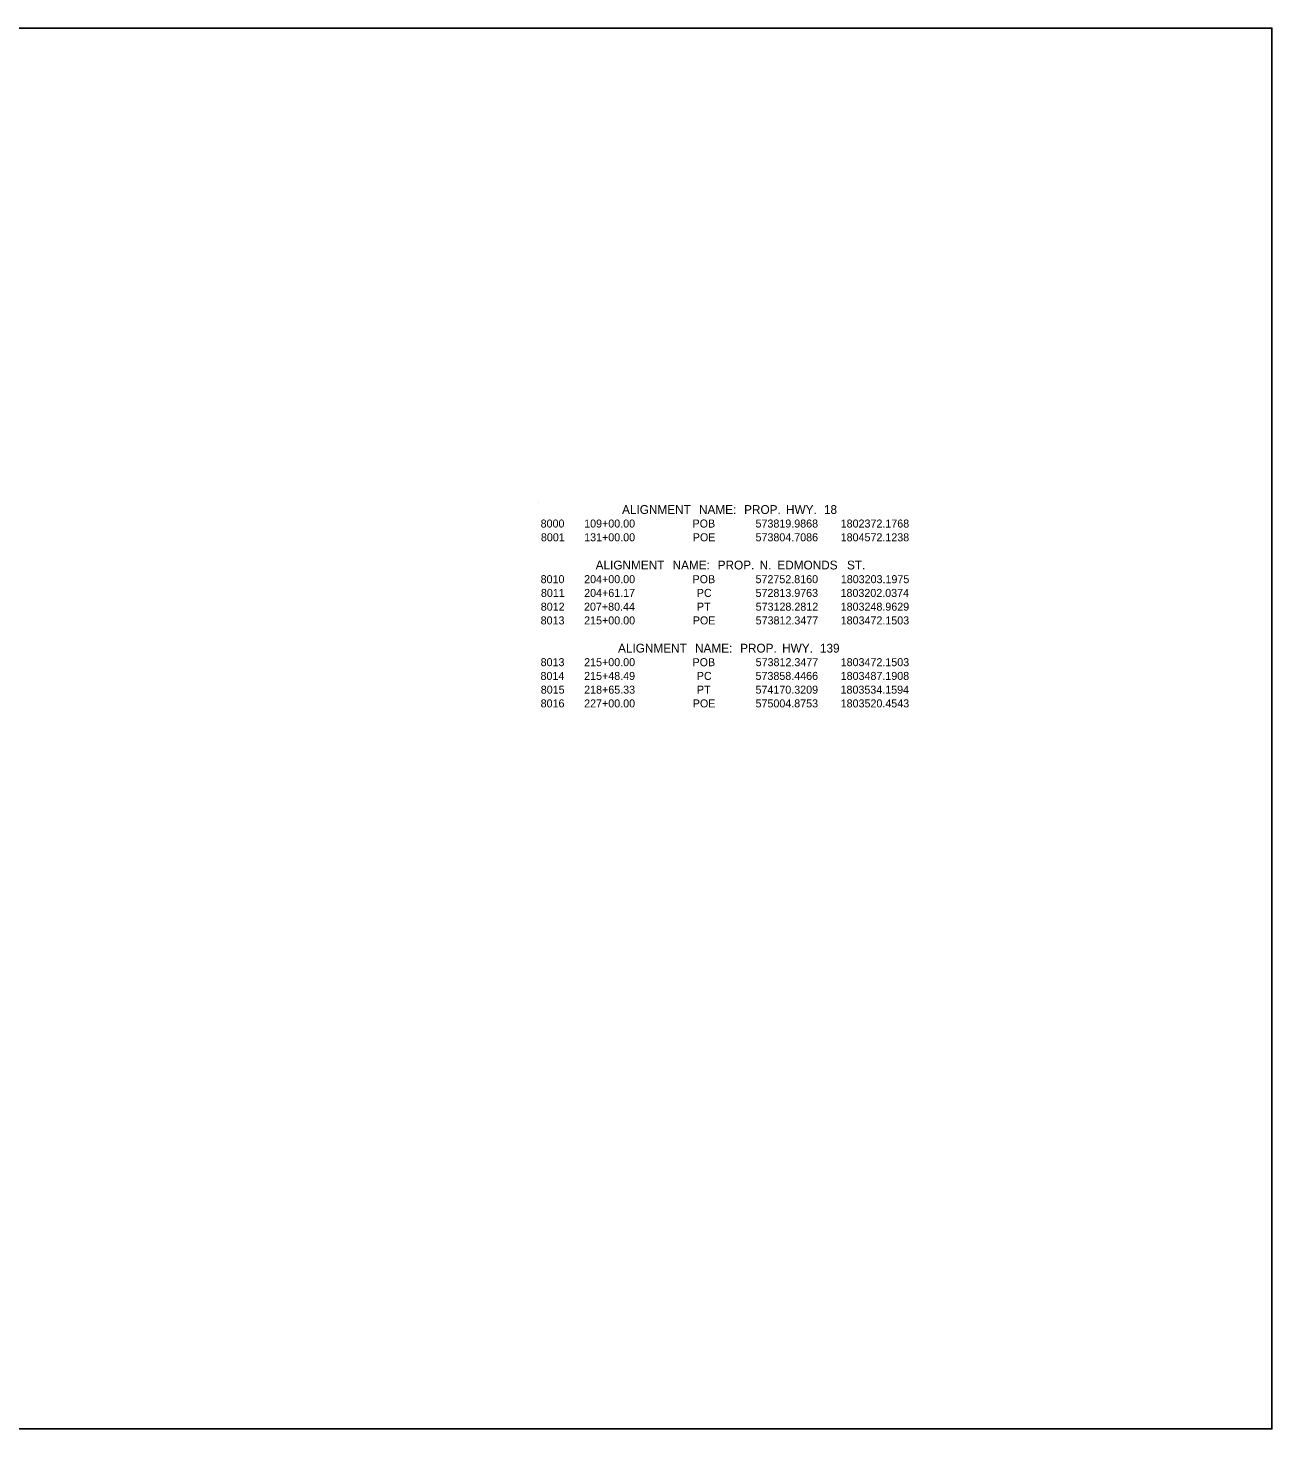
# Model space of a CAD drawing. Extents: x 1798464 to 1804463, y 572727 to 574861.
# Drawn here: x 1799396 to 1800328, y 573583 to 574633 of the extents above; entities that cross this region are included whole.
import ezdxf

# ---------------------------------------------------------------- set-up
doc = ezdxf.new("R2010")
doc.units = 0
for name, color, linetype in [('DSN_DRFT_Named-Boundary', 7, 'Continuous'), ('DSN_QNTY_Annotation', 7, 'Continuous'), ('S_BASELINE_ANNOT', 7, 'Continuous')]:
    doc.layers.add(name, color=color, linetype=linetype)

msp = doc.modelspace()

# ---------------------------------------------------------------- linework, layer by layer
at = {"layer": 'DSN_DRFT_Named-Boundary'}
msp.add_lwpolyline([(1798702.7, 573583), (1800327.7, 573583), (1800327.7, 574633), (1798702.7, 574633)], close=True, dxfattribs=at)
at = {"layer": 'S_BASELINE_ANNOT'}
msp.add_line((1799777.9, 574277.5), (1799777.9, 574277.5), dxfattribs=at)

# ---------------------------------------------------------------- texts
at = {"layer": 'DSN_QNTY_Annotation'}
for s, height, p in [('ALIGNMENT', 6.6, (1799840.8, 574268.8)), (' NAME:', 6.6, (1799896, 574268.8)), (' PROP.', 6.6, (1799929.8, 574268.8)), (' HWY.', 6.6, (1799961.2, 574268.8)), (' 18', 6.6, (1799989.6, 574268.8)), ('8000', 6, (1799779.8, 574258.6)), ('109+00.00', 6, (1799812.4, 574258.6)), ('POB', 6, (1799893.6, 574258.6)), ('573819.9868', 6, (1799940.8, 574258.6)), ('1802372.1768', 6, (1800004.6, 574258.6)), ('8001', 6, (1799780, 574248.3)), ('131+00.00', 6, (1799812.4, 574248.3)), ('POE', 6, (1799893.8, 574248.3)), ('573804.7086', 6, (1799940.8, 574248.3)), ('1804572.1238', 6, (1800004.6, 574248.3)), ('ALIGNMENT', 6.6, (1799821, 574227.2)), (' NAME:', 6.6, (1799876.2, 574227.2)), (' PROP.', 6.6, (1799910, 574227.2)), (' N.', 6.6, (1799941.4, 574227.2)), (' EDMONDS', 6.6, (1799954.7, 574227.2)), (' ST.', 6.6, (1800006.9, 574227.2)), ('8010', 6, (1799779.8, 574216.9)), ('204+00.00', 6, (1799812.4, 574216.9)), ('POB', 6, (1799893.6, 574216.9)), ('572752.8160', 6, (1799940.8, 574216.9)), ('1803203.1975', 6, (1800004.7, 574216.9)), ('8011', 6, (1799780, 574206.6)), ('204+61.17', 6, (1799812.4, 574206.6)), ('PC', 6, (1799896.8, 574206.6)), ('572813.9763', 6, (1799940.8, 574206.6)), ('1803202.0374', 6, (1800004.5, 574206.6)), ('8012', 6, (1799779.9, 574196.3)), ('207+80.44', 6, (1799812.3, 574196.3)), ('PT', 6, (1799896.9, 574196.3)), ('573128.2812', 6, (1799940.9, 574196.3)), ('1803248.9629', 6, (1800004.6, 574196.3)), ('8013', 6, (1799779.8, 574186)), ('215+00.00', 6, (1799812.4, 574186)), ('POE', 6, (1799893.8, 574186)), ('573812.3477', 6, (1799940.9, 574186)), ('1803472.1503', 6, (1800004.6, 574186)), ('ALIGNMENT', 6.6, (1799837.8, 574164.9)), (' NAME:', 6.6, (1799893, 574164.9)), (' PROP.', 6.6, (1799926.8, 574164.9)), (' HWY.', 6.6, (1799958.3, 574164.9)), (' 139', 6.6, (1799986.6, 574164.9)), ('8013', 6, (1799779.8, 574154.7)), ('215+00.00', 6, (1799812.4, 574154.7)), ('POB', 6, (1799893.6, 574154.7)), ('573812.3477', 6, (1799940.9, 574154.7)), ('1803472.1503', 6, (1800004.6, 574154.7)), ('8014', 6, (1799779.7, 574144.4)), ('8015', 6, (1799779.9, 574134.1)), ('215+48.49', 6, (1799812.4, 574144.4)), ('218+65.33', 6, (1799812.4, 574134.1)), ('PC', 6, (1799896.8, 574144.4)), ('PT', 6, (1799896.9, 574134.1)), ('573858.4466', 6, (1799940.8, 574144.4)), ('574170.3209', 6, (1799940.8, 574134.1)), ('1803534.1594', 6, (1800004.5, 574134.1)), ('1803487.1908', 6, (1800004.6, 574144.4)), ('8016', 6, (1799779.8, 574123.8)), ('227+00.00', 6, (1799812.4, 574123.8)), ('POE', 6, (1799893.8, 574123.8)), ('575004.8753', 6, (1799940.8, 574123.8)), ('1803520.4543', 6, (1800004.6, 574123.8))]:
    msp.add_text(s, height=height, dxfattribs=at).set_placement(p)

doc.saveas('drawing.dxf')
